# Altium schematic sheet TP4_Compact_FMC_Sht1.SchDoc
size B; SheetNumber: 1; SheetTotal: 2
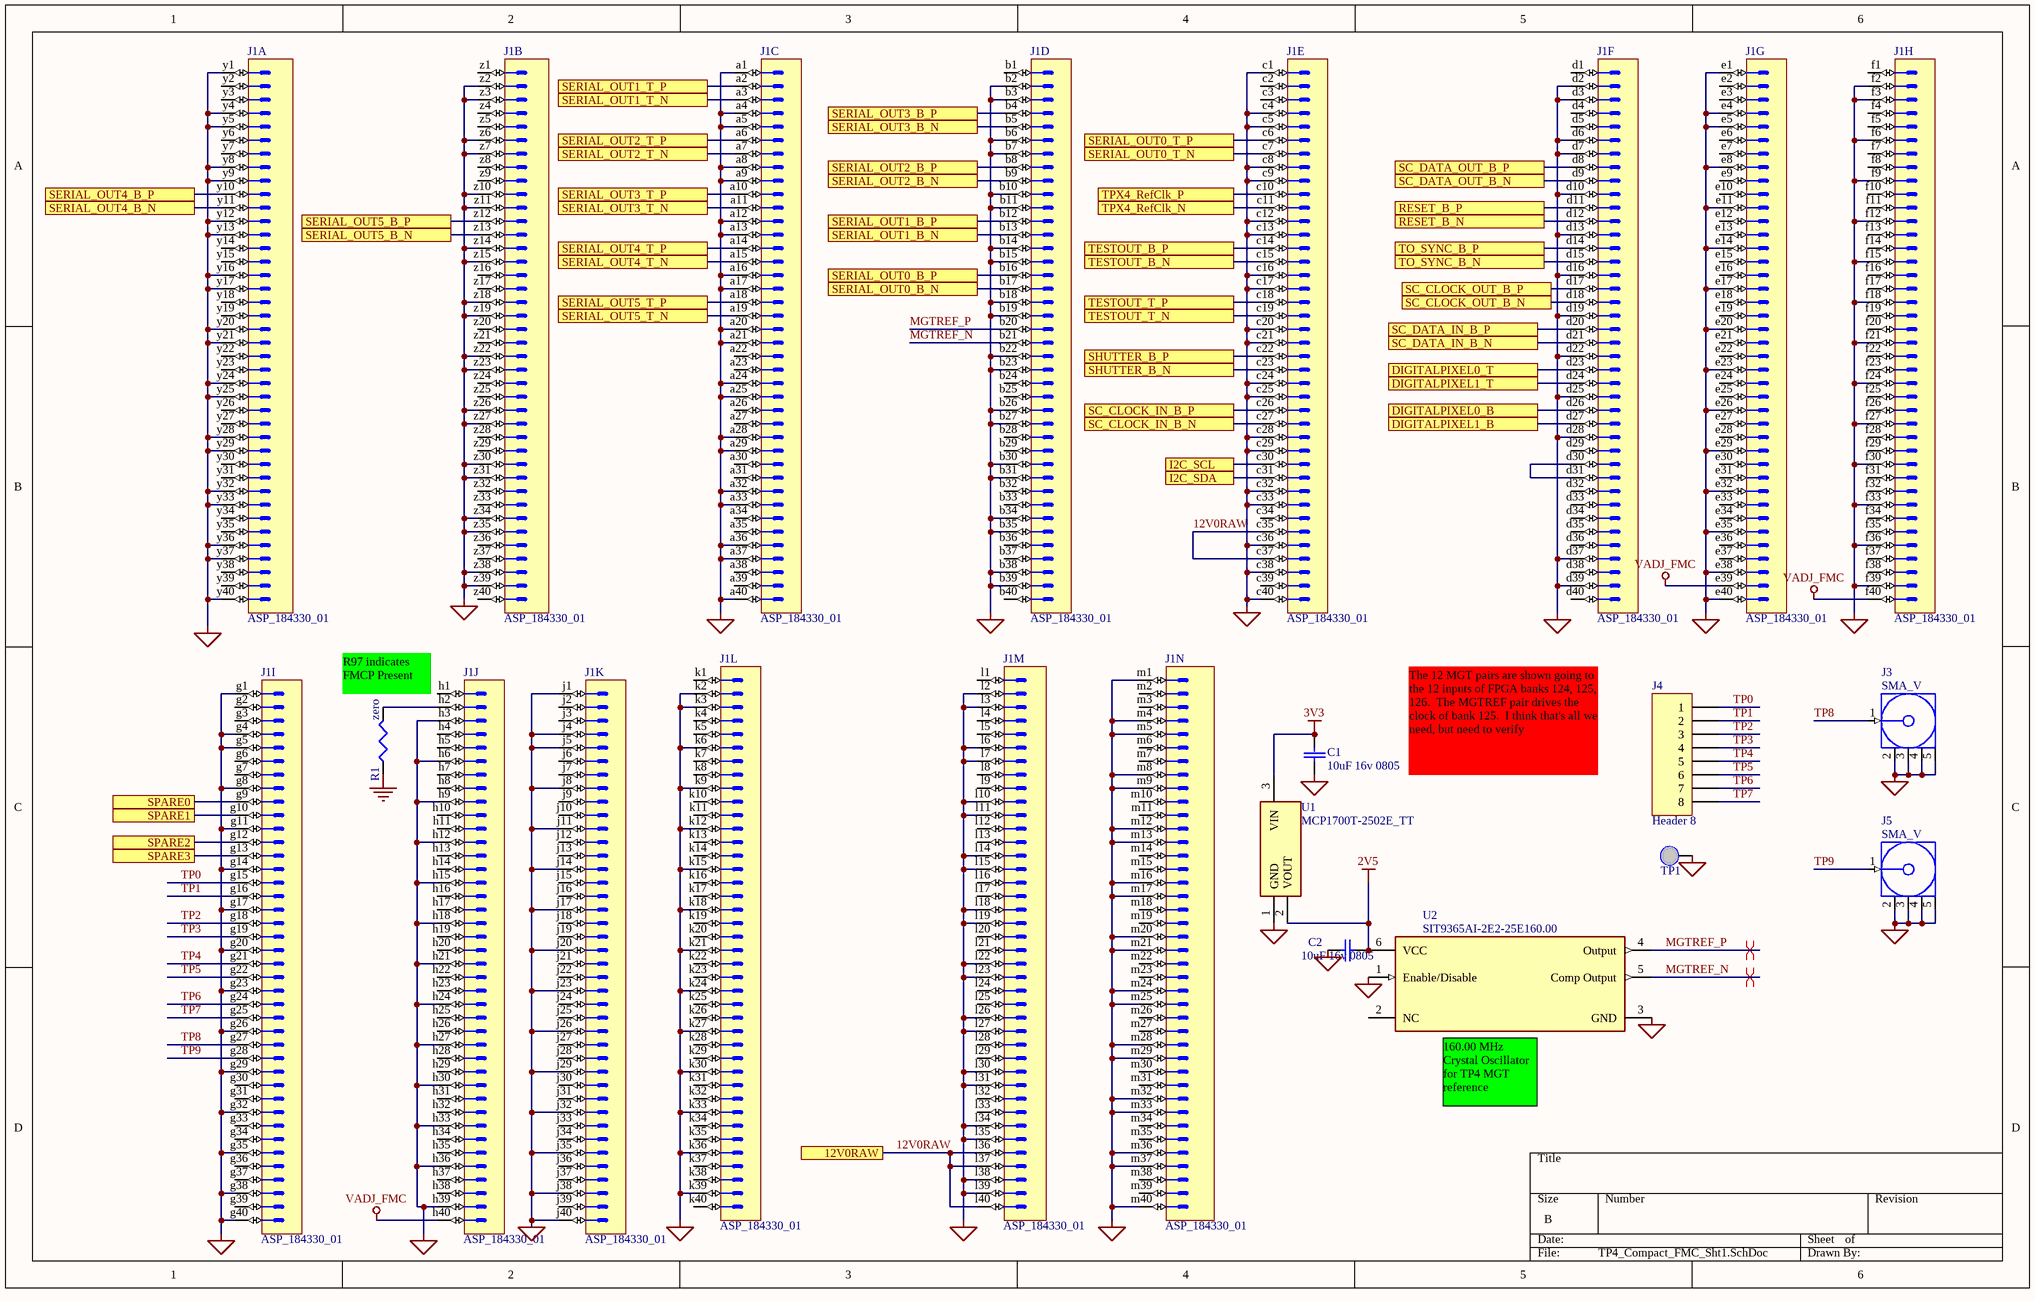
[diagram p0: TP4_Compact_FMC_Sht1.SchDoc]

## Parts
C1  value 10uF 16v 0805  [CAP0805]  (hidden comment: Cap)
C2  value 10uF 16v 0805  [CAP0805]  (hidden comment: Cap)
J1  ASP_184330_01  [SAMTEC_ASP_184330_01]  (parts A,B,C,D,E,F,G,H,I,J,K,L,M,N of 14)
J3  SMA_V  [SMA_Vert]
J4  Header 8  [HDR1X8]
J5  SMA_V  [SMA_Vert]
R1  value zero  [CAP0805]  (hidden comment: Res)
TP1  through-hole pad  [Pin1]  (value not drawn)
U1  MCP1700T-2502E_TT  [SOT95P237X112-3N]
U2  SIT9365AI-2E2-25E160.00  [osc_7mm_5mm]

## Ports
12V0RAW (see TP4_Compact_FMC_Sht2[1A]), DIGITALPIXEL0_B (see TP4_Compact_FMC_Sht2[6B]), DIGITALPIXEL0_T (see TP4_Compact_FMC_Sht2[6B]), DIGITALPIXEL1_B (see TP4_Compact_FMC_Sht2[6B]), DIGITALPIXEL1_T (see TP4_Compact_FMC_Sht2[6B]), I2C_SCL (see TP4_Compact_FMC_Sht2[4C]), I2C_SDA (see TP4_Compact_FMC_Sht2[6C]), RESET_B_N (see TP4_Compact_FMC_Sht2[4B]), RESET_B_P (see TP4_Compact_FMC_Sht2[4B]), SC_CLOCK_IN_B_N (see TP4_Compact_FMC_Sht2[4B]), SC_CLOCK_IN_B_P (see TP4_Compact_FMC_Sht2[4B]), SC_CLOCK_OUT_B_N (see TP4_Compact_FMC_Sht2[6B]), SC_CLOCK_OUT_B_P (see TP4_Compact_FMC_Sht2[6B]), SC_DATA_IN_B_N (see TP4_Compact_FMC_Sht2[6B]), SC_DATA_IN_B_P (see TP4_Compact_FMC_Sht2[6B]), SC_DATA_OUT_B_N (see TP4_Compact_FMC_Sht2[4B]), SC_DATA_OUT_B_P (see TP4_Compact_FMC_Sht2[4B]), SERIAL_OUT0_B_N (see TP4_Compact_FMC_Sht2[4A]), SERIAL_OUT0_B_P (see TP4_Compact_FMC_Sht2[4A]), SERIAL_OUT0_T_N (see TP4_Compact_FMC_Sht2[4A]), SERIAL_OUT0_T_P (see TP4_Compact_FMC_Sht2[4A]), SERIAL_OUT1_B_N (see TP4_Compact_FMC_Sht2[6A]), SERIAL_OUT1_B_P (see TP4_Compact_FMC_Sht2[6A]), SERIAL_OUT1_T_N (see TP4_Compact_FMC_Sht2[4A]), SERIAL_OUT1_T_P (see TP4_Compact_FMC_Sht2[4A]), SERIAL_OUT2_B_N (see TP4_Compact_FMC_Sht2[4A]), SERIAL_OUT2_B_P (see TP4_Compact_FMC_Sht2[4A]), SERIAL_OUT2_T_N (see TP4_Compact_FMC_Sht2[6A]), SERIAL_OUT2_T_P (see TP4_Compact_FMC_Sht2[6A]), SERIAL_OUT3_B_N (see TP4_Compact_FMC_Sht2[4A]), SERIAL_OUT3_B_P (see TP4_Compact_FMC_Sht2[4A]), SERIAL_OUT3_T_N (see TP4_Compact_FMC_Sht2[4A]), SERIAL_OUT3_T_P (see TP4_Compact_FMC_Sht2[4A]), SERIAL_OUT4_B_N (see TP4_Compact_FMC_Sht2[6A]), SERIAL_OUT4_B_P (see TP4_Compact_FMC_Sht2[6A]), SERIAL_OUT4_T_N (see TP4_Compact_FMC_Sht2[6A]), SERIAL_OUT4_T_P (see TP4_Compact_FMC_Sht2[6A]), SERIAL_OUT5_B_N (see TP4_Compact_FMC_Sht2[6A]), SERIAL_OUT5_B_P (see TP4_Compact_FMC_Sht2[6A]), SERIAL_OUT5_T_N (see TP4_Compact_FMC_Sht2[6A]), SERIAL_OUT5_T_P (see TP4_Compact_FMC_Sht2[6A]), SHUTTER_B_N (see TP4_Compact_FMC_Sht2[6B]), SHUTTER_B_P (see TP4_Compact_FMC_Sht2[6B]), SPARE0 (see TP4_Compact_FMC_Sht2[6B]), SPARE1 (see TP4_Compact_FMC_Sht2[6B]), SPARE2 (see TP4_Compact_FMC_Sht2[6B]), SPARE3 (see TP4_Compact_FMC_Sht2[6B]), TESTOUT_B_N (see TP4_Compact_FMC_Sht2[4B]), TESTOUT_B_P (see TP4_Compact_FMC_Sht2[4B]), TESTOUT_T_N (see TP4_Compact_FMC_Sht2[4B]), TESTOUT_T_P (see TP4_Compact_FMC_Sht2[4B]), TO_SYNC_B_N (see TP4_Compact_FMC_Sht2[4B]), TO_SYNC_B_P (see TP4_Compact_FMC_Sht2[4B]), TPX4_RefClk_N (see TP4_Compact_FMC_Sht2[4B]), TPX4_RefClk_P (see TP4_Compact_FMC_Sht2[4B])

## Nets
2V5: C2.1 U1.2(VOUT) U2.6(VCC)
3V3: C1.1 U1.3(VIN)
GND: C1.2 C2.2 J1.a1 J1.a4 J1.a5 J1.a8 J1.a9 J1.a12 J1.a13 J1.a16 J1.a17 J1.a20 J1.a21 J1.a24 J1.a25 J1.a28 J1.a29 J1.a32 J1.a33 J1.a36 J1.a37 J1.a40 J1.b2 J1.b3 J1.b6 J1.b7 J1.b10 J1.b11 J1.b14 J1.b15 J1.b18 J1.b19 J1.b22 J1.b23 J1.b26 J1.b27 J1.b30 J1.b31 J1.b34 J1.b35 J1.b38 J1.b39 J1.c1 J1.c4 J1.c5 J1.c8 J1.c9 J1.c12 J1.c13 J1.c16 J1.c17 J1.c20 J1.c21 J1.c24 J1.c25 J1.c28 J1.c29 J1.c32 J1.c33 J1.c36 J1.c38 J1.c40 J1.d2 J1.d3 J1.d6 J1.d7 J1.d10 J1.d13 J1.d16 J1.d19 J1.d22 J1.d25 J1.d28 J1.d37 J1.d39 J1.e1 J1.e4 J1.e5 J1.e8 J1.e11 J1.e14 J1.e17 J1.e20 J1.e23 J1.e26 J1.e29 J1.e32 J1.e35 J1.e38 J1.e40 J1.f2 J1.f3 J1.f6 J1.f9 J1.f12 J1.f15 J1.f18 J1.f21 J1.f24 J1.f27 J1.f30 J1.f33 J1.f36 J1.f39 J1.g1 J1.g4 J1.g5 J1.g8 J1.g11 J1.g14 J1.g17 J1.g20 J1.g23 J1.g26 J1.g29 J1.g32 J1.g35 J1.g38 J1.g40 J1.h3 J1.h6 J1.h9 J1.h12 J1.h15 J1.h18 J1.h21 J1.h24 J1.h27 J1.h30 J1.h33 J1.h36 J1.h39 J1.j1 J1.j4 J1.j5 J1.j8 J1.j11 J1.j14 J1.j17 J1.j20 J1.j23 J1.j26 J1.j29 J1.j32 J1.j35 J1.j38 J1.j40 J1.k2 J1.k3 J1.k6 J1.k9 J1.k12 J1.k15 J1.k18 J1.k21 J1.k24 J1.k27 J1.k30 J1.k33 J1.k36 J1.k39 J1.l2 J1.l3 J1.l6 J1.l7 J1.l10 J1.l11 J1.l14 J1.l15 J1.l18 J1.l19 J1.l22 J1.l23 J1.l26 J1.l27 J1.l30 J1.l31 J1.l34 J1.l35 J1.l38 J1.l39 J1.m1 J1.m4 J1.m5 J1.m8 J1.m9 J1.m12 J1.m13 J1.m16 J1.m17 J1.m20 J1.m21 J1.m24 J1.m25 J1.m28 J1.m29 J1.m32 J1.m33 J1.m36 J1.m37 J1.m40 J1.y1 J1.y4 J1.y5 J1.y8 J1.y9 J1.y12 J1.y13 J1.y16 J1.y17 J1.y20 J1.y21 J1.y24 J1.y25 J1.y28 J1.y29 J1.y32 J1.y33 J1.y36 J1.y37 J1.y40 J1.z2 J1.z3 J1.z6 J1.z7 J1.z10 J1.z11 J1.z14 J1.z15 J1.z18 J1.z19 J1.z22 J1.z23 J1.z26 J1.z27 J1.z30 J1.z31 J1.z34 J1.z35 J1.z38 J1.z39 J3.2(GND) J3.3(GND) J3.4(GND) J3.5(GND) J5.2(GND) J5.3(GND) J5.4(GND) J5.5(GND) R1.1 TP1.1 U1.1(GND) U2.1(Enable/Disable) U2.3(GND)
VADJ_FMC: J1.e39 J1.f40 J1.h40
12V0RAW: J1.c35 J1.c37 J1.l36 J1.l37 J1.l40 ; port 12V0RAW
DIGITALPIXEL0_B: J1.d26 ; port DIGITALPIXEL0_B
DIGITALPIXEL0_T: J1.d23 ; port DIGITALPIXEL0_T
DIGITALPIXEL1_B: J1.d27 ; port DIGITALPIXEL1_B
DIGITALPIXEL1_T: J1.d24 ; port DIGITALPIXEL1_T
I2C_SCL: J1.c30 ; port I2C_SCL
I2C_SDA: J1.c31 ; port I2C_SDA
MGTREF_N: J1.b21 U2.5(Comp_Output)
MGTREF_P: J1.b20 U2.4(Output)
RESET_B_N: J1.d12 ; port RESET_B_N
RESET_B_P: J1.d11 ; port RESET_B_P
SC_CLOCK_IN_B_N: J1.c27 ; port SC_CLOCK_IN_B_N
SC_CLOCK_IN_B_P: J1.c26 ; port SC_CLOCK_IN_B_P
SC_CLOCK_OUT_B_N: J1.d18 ; port SC_CLOCK_OUT_B_N
SC_CLOCK_OUT_B_P: J1.d17 ; port SC_CLOCK_OUT_B_P
SC_DATA_IN_B_N: J1.d21 ; port SC_DATA_IN_B_N
SC_DATA_IN_B_P: J1.d20 ; port SC_DATA_IN_B_P
SC_DATA_OUT_B_N: J1.d9 ; port SC_DATA_OUT_B_N
SC_DATA_OUT_B_P: J1.d8 ; port SC_DATA_OUT_B_P
SERIAL_OUT0_B_N: J1.b17 ; port SERIAL_OUT0_B_N
SERIAL_OUT0_B_P: J1.b16 ; port SERIAL_OUT0_B_P
SERIAL_OUT0_T_N: J1.c7 ; port SERIAL_OUT0_T_N
SERIAL_OUT0_T_P: J1.c6 ; port SERIAL_OUT0_T_P
SERIAL_OUT1_B_N: J1.b13 ; port SERIAL_OUT1_B_N
SERIAL_OUT1_B_P: J1.b12 ; port SERIAL_OUT1_B_P
SERIAL_OUT1_T_N: J1.a3 ; port SERIAL_OUT1_T_N
SERIAL_OUT1_T_P: J1.a2 ; port SERIAL_OUT1_T_P
SERIAL_OUT2_B_N: J1.b9 ; port SERIAL_OUT2_B_N
SERIAL_OUT2_B_P: J1.b8 ; port SERIAL_OUT2_B_P
SERIAL_OUT2_T_N: J1.a7 ; port SERIAL_OUT2_T_N
SERIAL_OUT2_T_P: J1.a6 ; port SERIAL_OUT2_T_P
SERIAL_OUT3_B_N: J1.b5 ; port SERIAL_OUT3_B_N
SERIAL_OUT3_B_P: J1.b4 ; port SERIAL_OUT3_B_P
SERIAL_OUT3_T_N: J1.a11 ; port SERIAL_OUT3_T_N
SERIAL_OUT3_T_P: J1.a10 ; port SERIAL_OUT3_T_P
SERIAL_OUT4_B_N: J1.y11 ; port SERIAL_OUT4_B_N
SERIAL_OUT4_B_P: J1.y10 ; port SERIAL_OUT4_B_P
SERIAL_OUT4_T_N: J1.a15 ; port SERIAL_OUT4_T_N
SERIAL_OUT4_T_P: J1.a14 ; port SERIAL_OUT4_T_P
SERIAL_OUT5_B_N: J1.z13 ; port SERIAL_OUT5_B_N
SERIAL_OUT5_B_P: J1.z12 ; port SERIAL_OUT5_B_P
SERIAL_OUT5_T_N: J1.a19 ; port SERIAL_OUT5_T_N
SERIAL_OUT5_T_P: J1.a18 ; port SERIAL_OUT5_T_P
SHUTTER_B_N: J1.c23 ; port SHUTTER_B_N
SHUTTER_B_P: J1.c22 ; port SHUTTER_B_P
SPARE0: J1.g9 ; port SPARE0
SPARE1: J1.g10 ; port SPARE1
SPARE2: J1.g12 ; port SPARE2
SPARE3: J1.g13 ; port SPARE3
TESTOUT_B_N: J1.c15 ; port TESTOUT_B_N
TESTOUT_B_P: J1.c14 ; port TESTOUT_B_P
TESTOUT_T_N: J1.c19 ; port TESTOUT_T_N
TESTOUT_T_P: J1.c18 ; port TESTOUT_T_P
TO_SYNC_B_N: J1.d15 ; port TO_SYNC_B_N
TO_SYNC_B_P: J1.d14 ; port TO_SYNC_B_P
TP0: J1.g15 J4.1
TP1: J1.g16 J4.2
TP2: J1.g18 J4.3
TP3: J1.g19 J4.4
TP4: J1.g21 J4.5
TP5: J1.g22 J4.6
TP6: J1.g24 J4.7
TP7: J1.g25 J4.8
TP8: J1.g27 J3.1(Signal)
TP9: J1.g28 J5.1(Signal)
TPX4_RefClk_N: J1.c11 ; port TPX4_RefClk_N
TPX4_RefClk_P: J1.c10 ; port TPX4_RefClk_P
NetJ1_d30: J1.d30 J1.d31
NetJ1_h2: J1.h2 R1.2

Not connected (* = marked no-connect by the designer): J1 a22 a23 a26 a27 a30 a31 a34 a35 a38 a39 b1 b24 b25 b28 b29 b32 b33 b36 b37 b40 c2 c3 c34 c39 d1 d4 d5 d29 d32 d33 d34 d35 d36 d38 d40 e2 e3 e6 e7 e9 e10 e12 e13 e15 e16 e18 e19 e21 e22 e24 e25 e27 e28 e30 e31 e33 e34 e36 e37 f1 f4 f5 f7 f8 f10 f11 f13 f14 f16 f17 f19 f20 f22 f23 f25 f26 f28 f29 f31 f32 f34 f35 f37 f38 g2 g3 g6 g7 g30 g31 g33 g34 g36 g37 g39 h1 h4 h5 h7 h8 h10 h11 h13 h14 h16 h17 h19 h20 h22 h23 h25 h26 h28 h29 h31 h32 h34 h35 h37 h38 j2 j3 j6 j7 j9 j10 j12 j13 j15 j16 j18 j19 j21 j22 j24 j25 j27 j28 j30 j31 j33 j34 j36 j37 j39 k1 k4 k5 k7 k8 k10 k11 k13 k14 k16 k17 k19 k20 k22 k23 k25 k26 k28 k29 k31 k32 k34 k35 k37 k38 k40 l1 l4 l5 l8 l9 l12 l13 l16 l17 l20 l21 l24 l25 l28 l29 l32 l33 m2 m3 m6 m7 m10 m11 m14 m15 m18 m19 m22 m23 m26 m27 m30 m31 m34 m35 m38 m39 y2 y3 y6 y7 y14 y15 y18 y19 y22 y23 y26 y27 y30 y31 y34 y35 y38 y39 z1 z4 z5 z8 z9 z16 z17 z20 z21 z24 z25 z28 z29 z32 z33 z36 z37 z40; U2 2(NC)

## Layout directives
differential pair: MGTREF_N, MGTREF_P

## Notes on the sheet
- R97 indicates FMCP Present
- The 12 MGT pairs are shown going to the 12 inputs of FPGA banks 124, 125, 126.  The MGTREF pair drives the clock of bank 125.  I think that's all we need, but need to verify
- (near U2) 160.00 MHz Crystal Oscillator for TP4 MGT reference

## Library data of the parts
C1 C2 = Cap: Capacitor, ceramic SM; OrderNo: 1276-2872-1-ND; CostEach: 0
J1 = FMCplus: CostEach: 0; OrderNo: SAM9173-ND
J3 J5 = COAX-F: Vertical mount SMA; PCB_Layout: Complies with manufacturer's recommendation.; DrillSize: Corresponds to nominal value.; OrderNo: SAM10718-ND
J4 = Header 8: Header, 8-Pin
R1 = Res3: Resistor; OrderNo: P0.0GCT; CostEach: 0
TP1 = testpoint: EM_PN: DNP
U1 = MCP1700T-2502E_TT: Integrated Circuit; Manufacturer_Name: Microchip; Manufacturer_Part_Number: MCP1700T-2502E/TT; OrderNo: MCP1700T-2502E/TTCT-ND
U2 = CCLD-033-50-100.000: OrderNo: 1473-SIT9365AI-2E2-25E160.000000-ND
